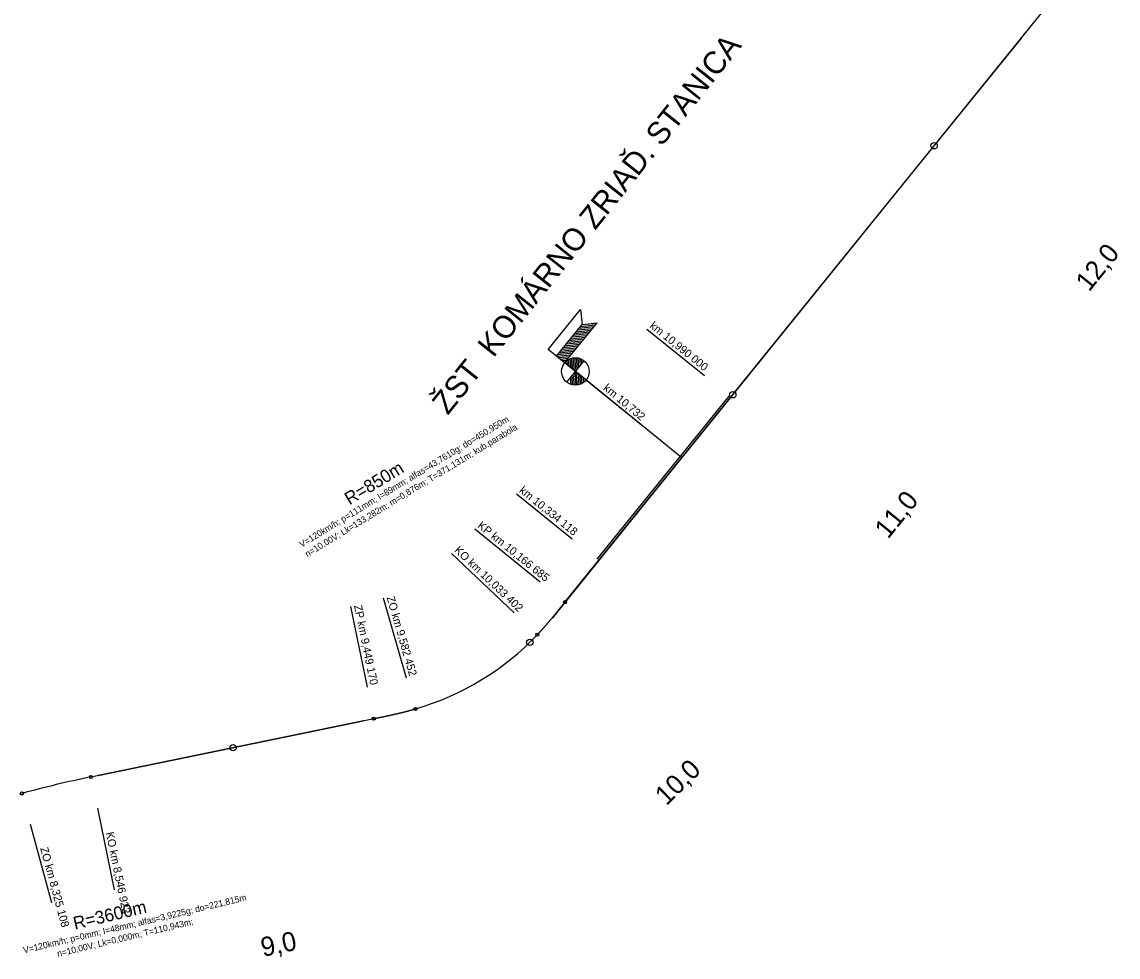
# Model space of a CAD drawing. Extents: x -504999 to -493096, y -1330712 to -1305226.
# Drawn here: x -500334 to -496910, y -1329550 to -1326629 of the extents above; entities that cross this region are included whole.
import ezdxf

# ---------------------------------------------------------------- set-up
doc = ezdxf.new("R2010")
doc.units = 0
for name, color, linetype in [('0_HM', 7, 'Continuous'), ('0_obluky', 7, 'Continuous'), ('0_popis oblukov', 7, 'Continuous'), ('0_STANICE', 7, 'Continuous'), ('0_stanicenie oblukov', 7, 'Continuous'), ('dotyčnice', 7, 'Continuous'), ('Level 1', 7, 'Continuous'), ('PHS', 7, 'Continuous')]:
    doc.layers.add(name, color=color, linetype=linetype)

msp = doc.modelspace()

# ---------------------------------------------------------------- linework, layer by layer
at = {"layer": '0_HM'}
for centre in [(-497485, -1327016.1), (-498113.9, -1327793.6), (-498747.9, -1328566.6), (-499674.8, -1328895.6)]:
    msp.add_circle(centre, 10, dxfattribs=at)
at = {"layer": '0_obluky'}
for p, q in [((-498638, -1328441.5), (-497128.1, -1326574.9)), ((-500118.6, -1328987.1), (-499234.9, -1328805))]:
    msp.add_line(p, q, dxfattribs=at)
for points in [[(-498638, -1328441.5), (-498638.6, -1328442.3), (-498639.3, -1328443.1), (-498639.9, -1328443.8), (-498640.5, -1328444.6), (-498641.1, -1328445.4), (-498641.8, -1328446.2), (-498642.4, -1328446.9), (-498643, -1328447.7), (-498643.7, -1328448.5), (-498644.3, -1328449.3), (-498644.9, -1328450.1), (-498645.6, -1328450.8), (-498646.2, -1328451.6), (-498646.8, -1328452.4), (-498647.4, -1328453.2), (-498648.1, -1328454), (-498648.7, -1328454.7), (-498649.3, -1328455.5), (-498650, -1328456.3), (-498650.6, -1328457.1), (-498651.2, -1328457.8), (-498651.9, -1328458.6), (-498652.5, -1328459.4), (-498653.1, -1328460.2), (-498653.8, -1328460.9), (-498654.4, -1328461.7), (-498655, -1328462.5), (-498655.7, -1328463.3), (-498656.3, -1328464.1), (-498656.9, -1328464.8), (-498657.6, -1328465.6), (-498658.2, -1328466.4), (-498658.8, -1328467.2), (-498659.5, -1328467.9), (-498660.1, -1328468.7), (-498660.7, -1328469.5), (-498661.4, -1328470.3), (-498662, -1328471), (-498662.6, -1328471.8), (-498663.3, -1328472.6), (-498663.9, -1328473.4), (-498664.5, -1328474.1), (-498665.2, -1328474.9), (-498665.8, -1328475.7), (-498666.4, -1328476.5), (-498667.1, -1328477.2), (-498667.7, -1328478), (-498668.4, -1328478.8), (-498669, -1328479.5), (-498669.6, -1328480.3), (-498670.3, -1328481.1), (-498670.9, -1328481.9), (-498671.5, -1328482.6), (-498672.2, -1328483.4), (-498672.8, -1328484.2), (-498673.5, -1328484.9), (-498674.1, -1328485.7), (-498674.8, -1328486.5), (-498675.4, -1328487.2), (-498676, -1328488), (-498676.7, -1328488.8), (-498677.3, -1328489.5), (-498678, -1328490.3), (-498678.6, -1328491.1), (-498679.3, -1328491.9), (-498679.9, -1328492.6), (-498680.5, -1328493.4), (-498681.2, -1328494.2), (-498681.8, -1328494.9), (-498682.5, -1328495.7), (-498683.1, -1328496.4), (-498683.8, -1328497.2), (-498684.4, -1328498), (-498685.1, -1328498.7), (-498685.7, -1328499.5), (-498686.4, -1328500.3), (-498687, -1328501), (-498687.7, -1328501.8), (-498688.3, -1328502.5), (-498689, -1328503.3), (-498689.6, -1328504.1), (-498690.3, -1328504.8), (-498690.9, -1328505.6), (-498691.6, -1328506.3), (-498692.2, -1328507.1), (-498692.9, -1328507.9), (-498693.6, -1328508.6), (-498694.2, -1328509.4), (-498694.9, -1328510.1), (-498695.5, -1328510.9), (-498696.2, -1328511.7), (-498696.8, -1328512.4), (-498697.5, -1328513.2), (-498698.2, -1328513.9), (-498698.8, -1328514.7), (-498699.5, -1328515.4), (-498700.1, -1328516.2), (-498700.8, -1328516.9), (-498701.5, -1328517.7), (-498702.1, -1328518.4), (-498702.8, -1328519.2), (-498703.5, -1328519.9), (-498704.1, -1328520.7), (-498704.8, -1328521.4), (-498705.5, -1328522.2), (-498706.1, -1328522.9), (-498706.8, -1328523.7), (-498707.5, -1328524.4), (-498708.1, -1328525.2), (-498708.8, -1328525.9), (-498709.5, -1328526.7), (-498710.2, -1328527.4), (-498710.8, -1328528.1), (-498711.5, -1328528.9), (-498712.2, -1328529.6), (-498712.9, -1328530.4), (-498713.5, -1328531.1), (-498714.2, -1328531.8), (-498714.9, -1328532.6), (-498715.6, -1328533.3), (-498716.3, -1328534.1), (-498716.9, -1328534.8), (-498717.6, -1328535.5), (-498718.3, -1328536.3), (-498719, -1328537), (-498719.7, -1328537.7), (-498720.3, -1328538.5), (-498721, -1328539.2), (-498721.7, -1328539.9), (-498722.4, -1328540.7), (-498723.1, -1328541.4), (-498723.8, -1328542.1), (-498724.5, -1328542.9)], [(-499234.9, -1328805), (-499233.9, -1328804.8), (-499232.9, -1328804.6), (-499232, -1328804.3), (-499231, -1328804.1), (-499230, -1328803.9), (-499229, -1328803.7), (-499228, -1328803.5), (-499227, -1328803.3), (-499226.1, -1328803.1), (-499225.1, -1328802.9), (-499224.1, -1328802.7), (-499223.1, -1328802.5), (-499222.1, -1328802.3), (-499221.2, -1328802.1), (-499220.2, -1328801.9), (-499219.2, -1328801.7), (-499218.2, -1328801.5), (-499217.2, -1328801.3), (-499216.3, -1328801.1), (-499215.3, -1328800.9), (-499214.3, -1328800.7), (-499213.3, -1328800.5), (-499212.3, -1328800.3), (-499211.4, -1328800.1), (-499210.4, -1328799.9), (-499209.4, -1328799.7), (-499208.4, -1328799.5), (-499207.4, -1328799.3), (-499206.5, -1328799.1), (-499205.5, -1328798.9), (-499204.5, -1328798.6), (-499203.5, -1328798.4), (-499202.5, -1328798.2), (-499201.6, -1328798), (-499200.6, -1328797.8), (-499199.6, -1328797.6), (-499198.6, -1328797.4), (-499197.6, -1328797.2), (-499196.7, -1328797), (-499195.7, -1328796.8), (-499194.7, -1328796.6), (-499193.7, -1328796.4), (-499192.7, -1328796.1), (-499191.8, -1328795.9), (-499190.8, -1328795.7), (-499189.8, -1328795.5), (-499188.8, -1328795.3), (-499187.8, -1328795.1), (-499186.9, -1328794.9), (-499185.9, -1328794.7), (-499184.9, -1328794.5), (-499183.9, -1328794.2), (-499183, -1328794), (-499182, -1328793.8), (-499181, -1328793.6), (-499180, -1328793.4), (-499179, -1328793.2), (-499178.1, -1328792.9), (-499177.1, -1328792.7), (-499176.1, -1328792.5), (-499175.1, -1328792.3), (-499174.2, -1328792.1), (-499173.2, -1328791.9), (-499172.2, -1328791.6), (-499171.2, -1328791.4), (-499170.2, -1328791.2), (-499169.3, -1328791), (-499168.3, -1328790.8), (-499167.3, -1328790.5), (-499166.3, -1328790.3), (-499165.4, -1328790.1), (-499164.4, -1328789.9), (-499163.4, -1328789.6), (-499162.4, -1328789.4), (-499161.5, -1328789.2), (-499160.5, -1328789), (-499159.5, -1328788.7), (-499158.5, -1328788.5), (-499157.6, -1328788.3), (-499156.6, -1328788), (-499155.6, -1328787.8), (-499154.6, -1328787.6), (-499153.7, -1328787.3), (-499152.7, -1328787.1), (-499151.7, -1328786.9), (-499150.7, -1328786.6), (-499149.8, -1328786.4), (-499148.8, -1328786.2), (-499147.8, -1328785.9), (-499146.8, -1328785.7), (-499145.9, -1328785.5), (-499144.9, -1328785.2), (-499143.9, -1328785), (-499142.9, -1328784.7), (-499142, -1328784.5), (-499141, -1328784.3), (-499140, -1328784), (-499139, -1328783.8), (-499138.1, -1328783.5), (-499137.1, -1328783.3), (-499136.1, -1328783), (-499135.2, -1328782.8), (-499134.2, -1328782.5), (-499133.2, -1328782.3), (-499132.2, -1328782), (-499131.3, -1328781.8), (-499130.3, -1328781.5), (-499129.3, -1328781.3), (-499128.4, -1328781), (-499127.4, -1328780.8), (-499126.4, -1328780.5), (-499125.5, -1328780.3), (-499124.5, -1328780), (-499123.5, -1328779.8), (-499122.5, -1328779.5), (-499121.6, -1328779.2), (-499120.6, -1328779), (-499119.6, -1328778.7), (-499118.7, -1328778.5), (-499117.7, -1328778.2), (-499116.7, -1328777.9), (-499115.8, -1328777.7), (-499114.8, -1328777.4), (-499113.8, -1328777.1), (-499112.9, -1328776.8), (-499111.9, -1328776.6), (-499110.9, -1328776.3), (-499110, -1328776), (-499109, -1328775.8), (-499108, -1328775.5), (-499107.1, -1328775.2), (-499106.1, -1328774.9), (-499105.1, -1328774.7)]]:
    msp.add_lwpolyline(points, dxfattribs=at)
for centre in [(-498638, -1328441.5), (-498724.5, -1328542.9), (-499105.1, -1328774.7), (-499234.9, -1328805), (-500118.6, -1328987.1), (-500334.3, -1329038.5)]:
    msp.add_circle(centre, 5, dxfattribs=at)
for centre, radius, start, end in [((-499341.4, -1327958.2), 850, 286.1392, 316.5363), ((-499391.9, -1332513), 3600, 101.6453, 105.1756)]:
    msp.add_arc(centre, radius, start, end, dxfattribs=at)
at = {"layer": '0_STANICE'}
for p, q in [((-498690.3, -1327652.3), (-498589.2, -1327527.4)), ((-498589.2, -1327527.4), (-498584.3, -1327573.8)), ((-498664.6, -1327673), (-498584.3, -1327573.8)), ((-498639, -1327693.8), (-498537.9, -1327568.9)), ((-498561.7, -1327598.3), (-498608.1, -1327603.2)), ((-498557.2, -1327592.8), (-498603.6, -1327597.7)), ((-498552.8, -1327587.3), (-498599.2, -1327592.2)), ((-498548.3, -1327581.8), (-498594.7, -1327586.7)), ((-498543.9, -1327576.3), (-498590.3, -1327581.2)), ((-498539.4, -1327570.8), (-498585.8, -1327575.7)), ((-498584.3, -1327573.8), (-498537.9, -1327568.9)), ((-498588.3, -1327631.2), (-498634.8, -1327636.1)), ((-498583.9, -1327625.8), (-498630.3, -1327630.6)), ((-498579.4, -1327620.3), (-498625.9, -1327625.1)), ((-498575, -1327614.8), (-498621.4, -1327619.6)), ((-498570.5, -1327609.3), (-498617, -1327614.2)), ((-498566.1, -1327603.8), (-498612.5, -1327608.7)), ((-498388.4, -1327896.7), (-498690.3, -1327652.3)), ((-498615, -1327664.2), (-498661.5, -1327669.1)), ((-498610.6, -1327658.7), (-498657, -1327663.6)), ((-498606.1, -1327653.2), (-498652.6, -1327658.1)), ((-498601.7, -1327647.7), (-498648.1, -1327652.6)), ((-498597.2, -1327642.2), (-498643.7, -1327647.1)), ((-498592.8, -1327636.7), (-498639.2, -1327641.6)), ((-498619.5, -1327669.7), (-498663.1, -1327674.3)), ((-498623.9, -1327675.2), (-498657.6, -1327678.8)), ((-498628.4, -1327680.7), (-498652.1, -1327683.2)), ((-498628.4, -1327680.7), (-498652.1, -1327683.2)), ((-498632.8, -1327686.2), (-498646.6, -1327687.7)), ((-498632.8, -1327686.2), (-498646.6, -1327687.7)), ((-498637.3, -1327691.7), (-498641.1, -1327692.1)), ((-498635.6, -1327696.6), (-498636.2, -1327690.7)), ((-498272.9, -1327990.1), (-498635.6, -1327696.5)), ((-498632.6, -1327754.3), (-498578.5, -1327687.4)), ((-498630.1, -1327701), (-498631.6, -1327686.6)), ((-498624.6, -1327705.5), (-498626.9, -1327683.5)), ((-498619.1, -1327709.9), (-498622.1, -1327681.2)), ((-498613.6, -1327714.3), (-498617.3, -1327679.5)), ((-498608.1, -1327718.8), (-498612.4, -1327678.4)), ((-498603.2, -1327717.9), (-498607.4, -1327677.9)), ((-498598.7, -1327712.4), (-498602.3, -1327678)), ((-498594.3, -1327706.9), (-498597.2, -1327678.7)), ((-498589.8, -1327701.4), (-498592.1, -1327680)), ((-498585.4, -1327695.9), (-498586.8, -1327682.1)), ((-498613.5, -1327763.1), (-498616.5, -1327734.4)), ((-498608.4, -1327763.8), (-498612.1, -1327728.9)), ((-498603.4, -1327763.8), (-498607.6, -1327723.4)), ((-498598.4, -1327763.3), (-498602.6, -1327723.2)), ((-498593.5, -1327762.2), (-498597.1, -1327727.7)), ((-498588.6, -1327760.4), (-498591.6, -1327732.1)), ((-498618.7, -1327761.8), (-498621, -1327739.9)), ((-498583.9, -1327758), (-498586.1, -1327736.6)), ((-498579.2, -1327754.9), (-498580.6, -1327741))]:
    msp.add_line(p, q, dxfattribs=at)
msp.add_circle((-498605.5, -1327720.9), 43, dxfattribs=at)
at = {"layer": '0_stanicenie oblukov'}
for p, q in [((-498715.7, -1328378.6), (-498919.6, -1328213.7)), ((-498797.1, -1328474.1), (-498992.2, -1328289.1)), ((-499132.9, -1328678.6), (-499205.1, -1328429.1)), ((-499255.1, -1328707), (-499307.1, -1328454.5)), ((-500098.4, -1329085), (-500046, -1329339.1)), ((-500308.1, -1329135), (-500241.8, -1329379.4))]:
    msp.add_line(p, q, dxfattribs=at)
at = {"layer": 'dotyčnice'}
for p, q in [((-498677.4, -1328490.2), (-497212.3, -1326679)), ((-500095.8, -1328982.4), (-499267.3, -1328811.6))]:
    msp.add_line(p, q, dxfattribs=at)
at = {"layer": 'Level 1'}
for points in [[(-497212.3, -1326679), (-497542.7, -1327087.2), (-498047.2, -1327710.5), (-498374.3, -1328114.9), (-498677.4, -1328490.2)], [(-499267.3, -1328811.6), (-500050.5, -1328973.1), (-500095.8, -1328982.4)]]:
    msp.add_lwpolyline(points, dxfattribs=at)
at = {"layer": 'PHS'}
for p, q in [((-498202.6, -1327734.7), (-498381.9, -1327589.7)), ((-498537.4, -1328307.5), (-498124.9, -1327797.6)), ((-498615.1, -1328244.7), (-498789.3, -1328103.7))]:
    msp.add_line(p, q, dxfattribs=at)

# ---------------------------------------------------------------- texts
at = {"layer": '0_HM'}
for s, rotation, p in [('12,0', 51.0302, (-497001.1, -1327474.3)), ('11,0', 51.0302, (-497629, -1328246.4)), ('10,0', 44.2848, (-498321.2, -1329078.5)), ('9,0', 11.6453, (-499581.5, -1329549))]:
    msp.add_text(s, height=60, rotation=rotation, dxfattribs=at).set_placement(p)
at = {"layer": '0_popis oblukov'}
for s, height, rotation, p in [('V=120km/h; p=111mm; I=89mm; alfas=43,7610g; do=450,950m', 20, 31.3378, (-499460.3, -1328271.1)), ('n=10,00V; Lk=133,282m; m=0,876m; T=371,131m; kub.parabola', 20, 31.3378, (-499442.4, -1328301.3)), ('R=850m', 40, 31.3378, (-499311, -1328139.2)), ('V=120km/h; p=0mm; I=48mm; alfas=3,9225g; do=221,815m', 20, 13.4105, (-500327.7, -1329538.2)), ('R=3600m', 40, 13.4105, (-500168.8, -1329464.3)), ('n=10,00V; Lk=0,000m; T=110,943m;', 20, 13.4105, (-500221.8, -1329548.9))]:
    msp.add_text(s, height=height, rotation=rotation, dxfattribs=at).set_placement(p)
at = {"layer": '0_STANICE'}
for s, height, rotation, p in [('ŽST  KOMÁRNO ZRIAĎ. STANICA', 70, 51.4627, (-499004, -1327859.3)), ('km 10,732', 25, 320.324, (-498520.6, -1327776.4))]:
    msp.add_text(s, height=height, rotation=rotation, dxfattribs=at).set_placement(p)
at = {"layer": '0_stanicenie oblukov'}
for s, rotation, p in [('KP km 10,166 685', 321.0302, (-498913.3, -1328206)), ('KO km 10,033 402', 316.5363, (-498985.4, -1328281.8)), ('ZP km 9,449 170', 281.6453, (-499297.3, -1328452.5)), ('ZO km 9,582 452', 286.1392, (-499195.5, -1328426.3)), ('KO km 8,546 923', 281.6453, (-500072.4, -1329161.4)), ('ZO km 8,325 108', 285.1756, (-500277.5, -1329209.6))]:
    msp.add_text(s, height=25, rotation=rotation, dxfattribs=at).set_placement(p)
at = {"layer": 'PHS'}
for s, p in [('km 10,990 000', (-498375.6, -1327582)), ('km 10,334 118', (-498783, -1328096))]:
    msp.add_text(s, height=25, rotation=321.0302, dxfattribs=at).set_placement(p)

doc.saveas('drawing.dxf')
